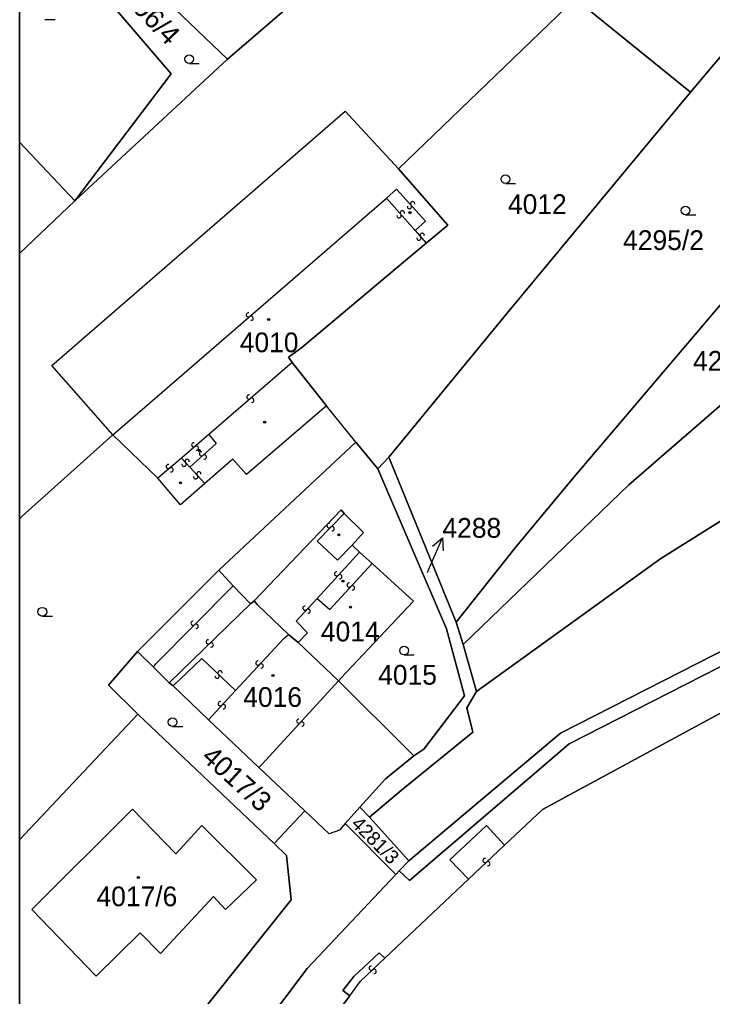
# Model space of a CAD drawing. Extents: x -598233 to -596890, y -1157848 to -1156431.
# Drawn here: x -598232.9 to -598173.3, y -1156881.8 to -1156797.7 of the extents above; entities that cross this region are included whole.
import ezdxf

# ---------------------------------------------------------------- set-up
doc = ezdxf.new("R2010")
doc.units = 0
for name, color, linetype in [('Level 1', 7, 'Continuous'), ('Level 13', 7, 'Continuous'), ('Level 3', 7, 'Continuous'), ('Level 4', 7, 'Continuous'), ('Level 5', 7, 'Continuous'), ('Level 57', 7, 'Continuous'), ('Level 60', 7, 'Continuous'), ('Vrstva 60', 7, 'Continuous'), ('zajmove_uzemi', 7, 'Continuous')]:
    doc.layers.add(name, color=color, linetype=linetype)

msp = doc.modelspace()

# ---------------------------------------------------------------- linework, layer by layer
at = {"layer": 'Level 1'}
for p, q in [((-598228.12, -1156813.32), (-598232.89, -1156808.242)), ((-598228.12, -1156813.32), (-598232.89, -1156817.837)), ((-598222.7, -1156857.49), (-598232.89, -1156868.324))]:
    msp.add_line(p, q, dxfattribs=at)
for points in [[(-598175.16, -1156803.94), (-598155.73, -1156780.94)], [(-598232.89, -1156783.763), (-598231.16, -1156785.61), (-598214.99, -1156801.12)], [(-598214.99, -1156801.12), (-598197.28, -1156785.85)], [(-598232.89, -1156787.117), (-598219.84, -1156802.38), (-598228.12, -1156813.32)], [(-598185.08, -1156795.9), (-598200.29, -1156810.56)], [(-598185.08, -1156795.9), (-598175.16, -1156803.94)], [(-598193.56, -1156855.54), (-598177.71, -1156844.1), (-598172.49, -1156840.81), (-598160.03, -1156833.51), (-598138.46, -1156822.74), (-598118.7, -1156809.71), (-598115.76, -1156807.85), (-598108.81, -1156797.54)], [(-598214.99, -1156801.12), (-598228.12, -1156813.32)], [(-598175.16, -1156803.94), (-598190.8, -1156822.82), (-598201.12, -1156835.36)], [(-598224.85, -1156833.46), (-598230.1, -1156827.49), (-598204.86, -1156805.59), (-598200.29, -1156810.56)], [(-598200.29, -1156810.56), (-598196.03, -1156815.4), (-598197.9, -1156816.96)], [(-598195.33, -1156849.57), (-598190.24, -1156843.19), (-598185.31, -1156837.25), (-598164.84, -1156813.13)], [(-598197.9, -1156816.96), (-598208.61, -1156825.92), (-598209.76, -1156826.76), (-598209.44, -1156827.23)], [(-598194.72, -1156851.49), (-598180.46, -1156837.75), (-598158.65, -1156818.85)], [(-598209.44, -1156827.23), (-598206.47, -1156830.96)], [(-598206.47, -1156830.96), (-598213.36, -1156836.87), (-598214.53, -1156835.54), (-598216.94, -1156837.64)], [(-598203.95, -1156834.08), (-598206.47, -1156830.96)], [(-598224.85, -1156833.46), (-598232.66, -1156840.44), (-598232.89, -1156840.668)], [(-598220.99, -1156837.18), (-598224.85, -1156833.46)], [(-598203.95, -1156834.08), (-598215.75, -1156845.11)], [(-598202.06, -1156836.37), (-598203.95, -1156834.08)], [(-598201.12, -1156835.36), (-598202.06, -1156836.37)], [(-598201.12, -1156835.36), (-598195.33, -1156849.57)], [(-598202.06, -1156836.37), (-598196.16, -1156850.14), (-598194.6, -1156855.93), (-598198.11, -1156860.5), (-598198.95, -1156861.08)], [(-598216.94, -1156837.64), (-598219.05, -1156839.48), (-598220.99, -1156837.18)], [(-598204.95, -1156840.21), (-598205.21, -1156839.9), (-598212.71, -1156847.73)], [(-598204.95, -1156840.21), (-598203.28, -1156841.87), (-598204.27, -1156842.94)], [(-598204.27, -1156842.94), (-598203.65, -1156843.55)], [(-598203.65, -1156843.55), (-598202.56, -1156844.52)], [(-598202.56, -1156844.52), (-598199, -1156847.76), (-598205.21, -1156854.37), (-598205.44, -1156854.64)], [(-598215.75, -1156845.11), (-598222.73, -1156852.1)], [(-598214.5, -1156846.44), (-598215.52, -1156845.35), (-598215.75, -1156845.11)], [(-598213.02, -1156848.01), (-598214.5, -1156846.44)], [(-598212.71, -1156847.73), (-598213.02, -1156848.01)], [(-598209.76, -1156850.63), (-598212.45, -1156848.06), (-598212.71, -1156847.73)], [(-598131.84, -1156849.33), (-598138.53, -1156851.73), (-598150.65, -1156850.55), (-598155.84, -1156850.09), (-598163.69, -1156850.8), (-598171.6, -1156851.6), (-598186.35, -1156859.13), (-598199.39, -1156870.12)], [(-598195.33, -1156849.57), (-598194.72, -1156851.49)], [(-598208.9, -1156851.34), (-598209.76, -1156850.63)], [(-598205.44, -1156854.64), (-598208.9, -1156851.34)], [(-598200.21, -1156870.99), (-598199.34, -1156871.82), (-598185.58, -1156860.05), (-598171.24, -1156852.74), (-598162.98, -1156851.97), (-598155.73, -1156851.28), (-598138.4, -1156852.95)], [(-598222.73, -1156852.1), (-598225.23, -1156855.01), (-598222.7, -1156857.49)], [(-598222.73, -1156852.1), (-598221.37, -1156853.46)], [(-598194.72, -1156851.49), (-598193.56, -1156855.54)], [(-598221.37, -1156853.46), (-598220.01, -1156854.8)], [(-598198.95, -1156861.08), (-598199.27, -1156860.76), (-598205.44, -1156854.64)], [(-598157.07, -1156860.47), (-598160.44, -1156854.25), (-598170.61, -1156856.35), (-598187.89, -1156865.71), (-598191.15, -1156868.77)], [(-598219.66, -1156855.07), (-598220.01, -1156854.8)], [(-598216.64, -1156857.98), (-598219.66, -1156855.07)], [(-598202.78, -1156866.35), (-598200.01, -1156864.05), (-598193.89, -1156859.04), (-598194.4, -1156856.94), (-598193.56, -1156855.54)], [(-598222.7, -1156857.49), (-598210.99, -1156868.62)], [(-598212.31, -1156862.09), (-598216.64, -1156857.98)], [(-598198.95, -1156861.08), (-598201.4, -1156863.06), (-598203.6, -1156865.49)], [(-598212.31, -1156862.09), (-598208.34, -1156865.83)], [(-598223.18, -1156865.68), (-598219.43, -1156869.51), (-598217.21, -1156867.07), (-598212.5, -1156871.75), (-598215.16, -1156874.3), (-598216.21, -1156873.19), (-598220.77, -1156878.1), (-598222.51, -1156876.33), (-598226.29, -1156880.05), (-598231.84, -1156874.3), (-598223.18, -1156865.68)], [(-598203.6, -1156865.49), (-598204.87, -1156866.92)], [(-598203.6, -1156865.49), (-598202.78, -1156866.35)], [(-598210.99, -1156868.62), (-598208.34, -1156865.83)], [(-598204.87, -1156866.92), (-598205.37, -1156867.47), (-598206.25, -1156867.79), (-598208.34, -1156865.83)], [(-598202.78, -1156866.35), (-598199.39, -1156870.12)], [(-598204.87, -1156866.92), (-598200.51, -1156871.31)], [(-598194.26, -1156871.69), (-598195.86, -1156870.04), (-598192.72, -1156867.09), (-598191.15, -1156868.77)], [(-598227.41, -1156895.92), (-598209.51, -1156873.47), (-598209.91, -1156869.66), (-598210.99, -1156868.62)], [(-598199.39, -1156870.12), (-598200.21, -1156870.99)], [(-598200.51, -1156871.31), (-598208.13, -1156879.38), (-598219.92, -1156895.06), (-598225, -1156901), (-598230.7, -1156904.8), (-598232.89, -1156905.647)], [(-598200.21, -1156870.99), (-598200.51, -1156871.31)], [(-598194.26, -1156871.69), (-598201.47, -1156878.51)], [(-598201.47, -1156878.51), (-598201.93, -1156878.03), (-598204.12, -1156880.09), (-598205.06, -1156881.27), (-598204.48, -1156881.73)], [(-598204.48, -1156881.73), (-598207.2, -1156885.32)]]:
    msp.add_lwpolyline(points, dxfattribs=at)
at = {"layer": 'Level 13'}
for centre, start, end in [((-598199.062, -1156813.558), 349.32564, 221.42364), ((-598199.951, -1156814.349), 349.08349, 221.18149), ((-598199.337, -1156813.802), 169.11119, 41.70119), ((-598200.228, -1156814.592), 168.86904, 41.45904), ((-598198.239, -1156816.281), 348.22811, 220.32611), ((-598198.52, -1156816.52), 168.01365, 40.60365), ((-598213.199, -1156823.129), 78.25558, 310.35358), ((-598212.96, -1156823.41), 258.04113, 130.63113), ((-598213.14, -1156830.19), 78.04828, 310.63828), ((-598212.901, -1156830.471), 258.26274, 130.36073), ((-598217.9, -1156834.31), 78.11904, 310.70904), ((-598217.66, -1156834.59), 258.33349, 130.43149), ((-598217.232, -1156835.082), 78.97845, 311.56845), ((-598216.988, -1156835.359), 259.1929, 131.2909), ((-598220.088, -1156836.178), 77.1292, 309.7192), ((-598219.853, -1156836.462), 257.34366, 129.44166), ((-598218.737, -1156835.983), 169.43197, 42.02197), ((-598218.462, -1156835.737), 349.64642, 221.74442), ((-598217.735, -1156837.065), 170.25616, 42.84616), ((-598217.464, -1156836.815), 350.47062, 222.56862), ((-598206.251, -1156841.27), 83.10103, 315.19903), ((-598205.989, -1156841.529), 262.88657, 135.47658), ((-598205.605, -1156845.414), 84.92754, 317.02554), ((-598205.335, -1156845.665), 264.71309, 137.30309), ((-598204.515, -1156846.374), 84.78376, 316.88176), ((-598204.245, -1156846.625), 264.56931, 137.15931), ((-598208.325, -1156848.374), 84.8224, 316.92039), ((-598208.055, -1156848.625), 264.60794, 137.19794), ((-598217.96, -1156849.669), 82.62966, 314.72766), ((-598217.7, -1156849.93), 262.41521, 135.00521), ((-598216.647, -1156851.267), 81.54121, 313.63921), ((-598216.392, -1156851.533), 261.32676, 133.91676), ((-598212.374, -1156853.093), 84.49383, 316.59183), ((-598215.631, -1156853.948), 353.49205, 225.59004), ((-598212.106, -1156853.346), 264.27938, 136.86938), ((-598215.888, -1156854.212), 173.27759, 45.86759), ((-598215.615, -1156856.594), 84.73898, 316.83698), ((-598215.345, -1156856.845), 264.52453, 137.11453), ((-598208.865, -1156858.095), 84.57544, 317.16544), ((-598208.595, -1156858.346), 264.7899, 136.88789), ((-598192.835, -1156870.095), 80.35354, 312.94354), ((-598192.585, -1156870.366), 260.56799, 132.66599), ((-598202.626, -1156879.366), 81.0997, 313.1977), ((-598202.373, -1156879.634), 260.88525, 133.47525)]:
    msp.add_arc(centre, 0.184, start, end, dxfattribs=at)
at = {"layer": 'Level 3'}
for points in [[(-598201.32, -1156813.09), (-598200.44, -1156812.3), (-598197.95, -1156815.07), (-598198.86, -1156815.85)], [(-598224.85, -1156833.46), (-598201.32, -1156813.09)], [(-598201.32, -1156813.09), (-598198.86, -1156815.85)], [(-598198.86, -1156815.85), (-598197.9, -1156816.96)], [(-598209.44, -1156827.23), (-598216.6, -1156833.43)], [(-598216.6, -1156833.43), (-598218.95, -1156835.47)], [(-598216.6, -1156833.43), (-598215.97, -1156834.2), (-598218.25, -1156836.24)], [(-598218.95, -1156835.47), (-598220.99, -1156837.18)], [(-598218.95, -1156835.47), (-598218.25, -1156836.24)], [(-598218.25, -1156836.24), (-598216.94, -1156837.64)], [(-598204.27, -1156842.94), (-598205.53, -1156844.24), (-598207.28, -1156842.6), (-598204.95, -1156840.21)], [(-598207.29, -1156847.53), (-598203.65, -1156843.55)], [(-598207.29, -1156847.53), (-598206.2, -1156848.48), (-598202.56, -1156844.52)], [(-598221.37, -1156853.46), (-598221.16, -1156853.16), (-598214.5, -1156846.44)], [(-598220.01, -1156854.8), (-598213.02, -1156848.01)], [(-598208.9, -1156851.34), (-598208.1, -1156850.49), (-598209.08, -1156849.48), (-598207.29, -1156847.53)], [(-598214.32, -1156855.46), (-598210.16, -1156850.98), (-598209.76, -1156850.63)], [(-598219.66, -1156855.07), (-598217.19, -1156852.7), (-598214.32, -1156855.46)], [(-598205.44, -1156854.64), (-598212.02, -1156861.8), (-598212.31, -1156862.09)], [(-598216.64, -1156857.98), (-598214.32, -1156855.46)], [(-598191.15, -1156868.77), (-598194.26, -1156871.69)], [(-598204.48, -1156881.73), (-598203.54, -1156880.49), (-598201.47, -1156878.51)]]:
    msp.add_lwpolyline(points, dxfattribs=at)
at = {"layer": 'Level 5'}
for p, q in [((-598230.7, -1156797.7), (-598229.825, -1156797.7)), ((-598218.3, -1156801.48), (-598217.425, -1156801.48)), ((-598191.08, -1156811.82), (-598190.205, -1156811.82)), ((-598175.58, -1156814.52), (-598174.705, -1156814.52)), ((-598230.93, -1156849.05), (-598230.055, -1156849.05)), ((-598199.8, -1156852.4), (-598198.925, -1156852.4)), ((-598219.72, -1156858.56), (-598218.845, -1156858.56))]:
    msp.add_line(p, q, dxfattribs=at)
for centre, radius in [((-598218.3, -1156801.105), 0.375), ((-598191.08, -1156811.445), 0.375), ((-598199.29, -1156814.32), 0.09), ((-598199.29, -1156814.32), 0.0521), ((-598175.58, -1156814.145), 0.375), ((-598211.45, -1156823.52), 0.09), ((-598211.45, -1156823.52), 0.0521), ((-598211.8, -1156832.36), 0.09), ((-598211.8, -1156832.36), 0.0521), ((-598217.43, -1156834.79), 0.09), ((-598217.43, -1156834.79), 0.0521), ((-598219.04, -1156837.58), 0.09), ((-598219.04, -1156837.58), 0.0521), ((-598205.41, -1156842.06), 0.09), ((-598205.41, -1156842.06), 0.0521), ((-598205.06, -1156846.04), 0.09), ((-598205.06, -1156846.04), 0.0521), ((-598230.93, -1156848.675), 0.375), ((-598204.41, -1156848.29), 0.09), ((-598204.41, -1156848.29), 0.0521), ((-598199.8, -1156852.025), 0.375), ((-598211.08, -1156854.17), 0.09), ((-598211.08, -1156854.17), 0.0521), ((-598219.72, -1156858.185), 0.375), ((-598222.67, -1156871.55), 0.09), ((-598222.67, -1156871.55), 0.0521)]:
    msp.add_circle(centre, radius, dxfattribs=at)
at = {"layer": 'Level 57'}
for p, q in [((-598197.684, -1156845.066), (-598196.5, -1156842.31)), ((-598197.78, -1156845.29), (-598197.684, -1156845.066))]:
    msp.add_line(p, q, dxfattribs=at)
msp.add_lwpolyline([(-598197.354, -1156843.031), (-598196.5, -1156842.31), (-598196.435, -1156843.426)], dxfattribs=at)
at = {"layer": 'Level 60'}
for points in [[(-598190.8, -1156822.82), (-598175.16, -1156803.94), (-598155.73, -1156780.94), (-598145.59, -1156788.78), (-598152.39, -1156798.08), (-598154.3, -1156800.35), (-598161.63, -1156809.25), (-598164.84, -1156813.13), (-598185.31, -1156837.25), (-598190.24, -1156843.19), (-598195.33, -1156849.57), (-598201.12, -1156835.36)], [(-598196.03, -1156815.4), (-598200.29, -1156810.56), (-598185.08, -1156795.9), (-598175.16, -1156803.94), (-598190.8, -1156822.82), (-598201.12, -1156835.36), (-598202.06, -1156836.37), (-598203.95, -1156834.08), (-598206.47, -1156830.96), (-598209.44, -1156827.23), (-598209.76, -1156826.76), (-598208.61, -1156825.92), (-598197.9, -1156816.96)], [(-598230.1, -1156827.49), (-598204.86, -1156805.59), (-598200.29, -1156810.56), (-598196.03, -1156815.4), (-598197.9, -1156816.96), (-598208.61, -1156825.92), (-598209.76, -1156826.76), (-598209.44, -1156827.23), (-598206.47, -1156830.96), (-598213.36, -1156836.87), (-598214.53, -1156835.54), (-598216.94, -1156837.64), (-598219.05, -1156839.48), (-598220.99, -1156837.18), (-598224.85, -1156833.46)], [(-598194.72, -1156851.49), (-598195.33, -1156849.57), (-598190.24, -1156843.19), (-598185.31, -1156837.25), (-598164.84, -1156813.13), (-598158.65, -1156818.85), (-598180.46, -1156837.75)], [(-598203.95, -1156834.08), (-598202.06, -1156836.37), (-598196.16, -1156850.14), (-598194.6, -1156855.93), (-598198.11, -1156860.5), (-598198.95, -1156861.08), (-598199.27, -1156860.76), (-598205.44, -1156854.64), (-598205.21, -1156854.37), (-598199, -1156847.76), (-598202.56, -1156844.52), (-598203.65, -1156843.55), (-598204.27, -1156842.94), (-598203.28, -1156841.87), (-598204.95, -1156840.21), (-598205.21, -1156839.9), (-598212.71, -1156847.73), (-598213.02, -1156848.01), (-598214.5, -1156846.44), (-598215.52, -1156845.35), (-598215.75, -1156845.11)], [(-598202.06, -1156836.37), (-598201.12, -1156835.36), (-598195.33, -1156849.57), (-598194.72, -1156851.49), (-598193.56, -1156855.54), (-598194.4, -1156856.94), (-598193.89, -1156859.04), (-598200.01, -1156864.05), (-598202.78, -1156866.35), (-598203.6, -1156865.49), (-598201.4, -1156863.06), (-598198.95, -1156861.08), (-598198.11, -1156860.5), (-598194.6, -1156855.93), (-598196.16, -1156850.14)], [(-598205.21, -1156839.9), (-598204.95, -1156840.21), (-598203.28, -1156841.87), (-598204.27, -1156842.94), (-598203.65, -1156843.55), (-598202.56, -1156844.52), (-598199, -1156847.76), (-598205.21, -1156854.37), (-598205.44, -1156854.64), (-598208.9, -1156851.34), (-598209.76, -1156850.63), (-598212.45, -1156848.06), (-598212.71, -1156847.73)], [(-598222.73, -1156852.1), (-598215.75, -1156845.11), (-598215.52, -1156845.35), (-598214.5, -1156846.44), (-598213.02, -1156848.01), (-598212.71, -1156847.73), (-598212.45, -1156848.06), (-598209.76, -1156850.63), (-598208.9, -1156851.34), (-598205.44, -1156854.64), (-598199.27, -1156860.76), (-598198.95, -1156861.08), (-598201.4, -1156863.06), (-598203.6, -1156865.49), (-598204.87, -1156866.92), (-598205.37, -1156867.47), (-598206.25, -1156867.79), (-598208.34, -1156865.83), (-598212.31, -1156862.09), (-598216.64, -1156857.98), (-598219.66, -1156855.07), (-598220.01, -1156854.8), (-598221.37, -1156853.46)], [(-598138.53, -1156851.73), (-598131.84, -1156849.33), (-598120.16, -1156868.28), (-598121.01, -1156869.19), (-598132.23, -1156850.98), (-598138.4, -1156852.95), (-598155.73, -1156851.28), (-598162.98, -1156851.97), (-598171.24, -1156852.74), (-598185.58, -1156860.05), (-598199.34, -1156871.82), (-598200.21, -1156870.99), (-598199.39, -1156870.12), (-598186.35, -1156859.13), (-598171.6, -1156851.6), (-598163.69, -1156850.8), (-598155.84, -1156850.09), (-598150.65, -1156850.55)], [(-598216.64, -1156857.98), (-598212.31, -1156862.09), (-598208.34, -1156865.83), (-598210.99, -1156868.62), (-598222.7, -1156857.49), (-598225.23, -1156855.01), (-598222.73, -1156852.1), (-598221.37, -1156853.46), (-598220.01, -1156854.8), (-598219.66, -1156855.07)], [(-598223.18, -1156865.68), (-598219.43, -1156869.51), (-598217.21, -1156867.07), (-598212.5, -1156871.75), (-598215.16, -1156874.3), (-598216.21, -1156873.19), (-598220.77, -1156878.1), (-598222.51, -1156876.33), (-598226.29, -1156880.05), (-598231.84, -1156874.3)], [(-598200.51, -1156871.31), (-598204.87, -1156866.92), (-598203.6, -1156865.49), (-598202.78, -1156866.35), (-598199.39, -1156870.12), (-598200.21, -1156870.99)]]:
    msp.add_lwpolyline(points, close=True, dxfattribs=at)
for points in [[(-598155.73, -1156780.94), (-598175.16, -1156803.94), (-598185.08, -1156795.9)], [(-598108.81, -1156797.54), (-598115.76, -1156807.85), (-598118.7, -1156809.71), (-598138.46, -1156822.74), (-598160.03, -1156833.51), (-598172.49, -1156840.81), (-598177.71, -1156844.1), (-598193.56, -1156855.54), (-598194.72, -1156851.49), (-598180.46, -1156837.75), (-598158.65, -1156818.85), (-598158.31, -1156818.54), (-598154.36, -1156815.18), (-598145.87, -1156807.79), (-598143.19, -1156804.8), (-598135.67, -1156796.45)], [(-598131.84, -1156849.33), (-598138.53, -1156851.73), (-598150.65, -1156850.55), (-598155.84, -1156850.09), (-598163.69, -1156850.8), (-598171.6, -1156851.6), (-598186.35, -1156859.13), (-598199.39, -1156870.12), (-598202.78, -1156866.35), (-598200.01, -1156864.05), (-598193.89, -1156859.04), (-598194.4, -1156856.94), (-598193.56, -1156855.54), (-598177.71, -1156844.1), (-598172.49, -1156840.81), (-598160.03, -1156833.51), (-598138.46, -1156822.74), (-598118.7, -1156809.71)]]:
    msp.add_lwpolyline(points, dxfattribs=at)
at = {"layer": 'Vrstva 60'}
for points in [[(-598045.825, -1156430.856), (-598232.89, -1156430.856), (-598232.89, -1157835.582)], [(-598171.24, -1156852.74), (-598185.58, -1156860.05), (-598199.34, -1156871.82), (-598200.21, -1156870.99), (-598200.51, -1156871.31), (-598208.13, -1156879.38), (-598219.92, -1156895.06)], [(-598171.12, -1156888.14), (-598160.07, -1156873.55), (-598159.86, -1156873.27), (-598157.12, -1156878.33), (-598132.24, -1156864.85), (-598135.14, -1156859.49), (-598135.17, -1156853.14), (-598138.57, -1156853.16), (-598146.44, -1156857.42), (-598155.1, -1156862.11), (-598157.07, -1156860.47), (-598160.44, -1156854.25), (-598170.61, -1156856.35), (-598187.89, -1156865.71), (-598191.15, -1156868.77), (-598192.72, -1156867.09), (-598195.86, -1156870.04), (-598194.26, -1156871.69), (-598201.47, -1156878.51), (-598201.93, -1156878.03), (-598204.12, -1156880.09), (-598205.06, -1156881.27), (-598204.48, -1156881.73), (-598207.2, -1156885.32)], [(-598207.2, -1156885.32), (-598204.48, -1156881.73), (-598205.06, -1156881.27), (-598204.12, -1156880.09), (-598201.93, -1156878.03), (-598201.47, -1156878.51), (-598194.26, -1156871.69), (-598195.86, -1156870.04), (-598192.72, -1156867.09), (-598191.15, -1156868.77), (-598187.89, -1156865.71), (-598170.61, -1156856.35)]]:
    msp.add_lwpolyline(points, dxfattribs=at)
for points in [[(-598232.89, -1156783.763), (-598231.16, -1156785.61), (-598214.99, -1156801.12), (-598197.28, -1156785.85), (-598192.6, -1156781.63), (-598195.22, -1156780.11), (-598196.16, -1156779.56), (-598195.39, -1156778.85), (-598208.41, -1156753.61), (-598215.76, -1156765.48), (-598216.48, -1156766.53), (-598211.35, -1156770.76), (-598207.29, -1156774.1), (-598209.37, -1156776.72), (-598211.65, -1156779.47), (-598213.51, -1156782.03), (-598215.6, -1156784.91), (-598217.76, -1156787.6), (-598219.79, -1156790.16), (-598224, -1156786.77), (-598229.89, -1156782.5), (-598232.89, -1156780.343)], [(-598232.89, -1156783.763), (-598232.89, -1156787.117), (-598219.84, -1156802.38), (-598228.12, -1156813.32), (-598214.99, -1156801.12), (-598231.16, -1156785.61)], [(-598232.89, -1156817.837), (-598232.89, -1156840.668), (-598232.66, -1156840.44), (-598224.85, -1156833.46), (-598230.1, -1156827.49), (-598204.86, -1156805.59), (-598200.29, -1156810.56), (-598185.08, -1156795.9), (-598197.28, -1156785.85), (-598214.99, -1156801.12), (-598228.12, -1156813.32)], [(-598232.89, -1156787.117), (-598232.89, -1156792.379), (-598231.86, -1156793.49), (-598232.89, -1156794.462), (-598232.89, -1156808.242), (-598228.12, -1156813.32), (-598219.84, -1156802.38)], [(-598232.89, -1156808.242), (-598232.89, -1156817.837), (-598228.12, -1156813.32)], [(-598232.89, -1156840.668), (-598232.89, -1156868.324), (-598222.7, -1156857.49), (-598225.23, -1156855.01), (-598222.73, -1156852.1), (-598215.75, -1156845.11), (-598203.95, -1156834.08), (-598206.47, -1156830.96), (-598213.36, -1156836.87), (-598214.53, -1156835.54), (-598216.94, -1156837.64), (-598219.05, -1156839.48), (-598220.99, -1156837.18), (-598224.85, -1156833.46), (-598232.66, -1156840.44)], [(-598232.89, -1156868.324), (-598232.89, -1156885.695), (-598227.41, -1156895.92), (-598209.51, -1156873.47), (-598209.91, -1156869.66), (-598210.99, -1156868.62), (-598222.7, -1156857.49)], [(-598217.21, -1156867.07), (-598212.5, -1156871.75), (-598215.16, -1156874.3), (-598216.21, -1156873.19), (-598220.77, -1156878.1), (-598222.51, -1156876.33), (-598226.29, -1156880.05), (-598231.84, -1156874.3), (-598223.18, -1156865.68), (-598219.43, -1156869.51)], [(-598232.89, -1156900.551), (-598232.89, -1156905.647), (-598230.7, -1156904.8), (-598225, -1156901), (-598219.92, -1156895.06), (-598208.13, -1156879.38), (-598200.51, -1156871.31), (-598204.87, -1156866.92), (-598205.37, -1156867.47), (-598206.25, -1156867.79), (-598208.34, -1156865.83), (-598210.99, -1156868.62), (-598209.91, -1156869.66), (-598209.51, -1156873.47), (-598227.41, -1156895.92), (-598232.3, -1156900.27)]]:
    msp.add_lwpolyline(points, close=True, dxfattribs=at)
at = {"layer": 'zajmove_uzemi'}
msp.add_lwpolyline([(-598232.89, -1156430.856), (-596890.462, -1156430.856), (-596890.462, -1157848.461), (-598232.89, -1157848.461)], close=True, dxfattribs=at)

# ---------------------------------------------------------------- texts
at = {"layer": 'Level 4'}
for s, height, rotation, p in [('3996/4', 1.7, 313.80003, (-598224.97, -1156795)), ('4017/3', 1.7, 317.7, (-598217.33, -1156861.33)), ('4281/3', 1.2, 314.80353, (-598204.421, -1156867.027))]:
    msp.add_text(s, height=height, rotation=rotation, dxfattribs=at).set_placement(p)
for s, height, p in [('4012', 1.7, (-598190.86, -1156814.44)), ('4295/2', 1.7, (-598180.95, -1156817.54)), ('4010', 1.7, (-598213.94, -1156826.34)), ('4294', 1.7, (-598174.93, -1156827.93)), ('4288', 0.1, (-598197.78, -1156845.29)), ('4014', 1.7, (-598206.96, -1156851.23)), ('4015', 1.7, (-598202.03, -1156854.96)), ('4016', 1.7, (-598213.64, -1156856.87)), ('4017/6', 1.7, (-598226.268, -1156874.03))]:
    msp.add_text(s, height=height, dxfattribs=at).set_placement(p)
at = {"layer": 'Level 57'}
msp.add_text('4288', height=1.7, dxfattribs=at).set_placement((-598196.5, -1156842.31))

doc.saveas('drawing.dxf')
